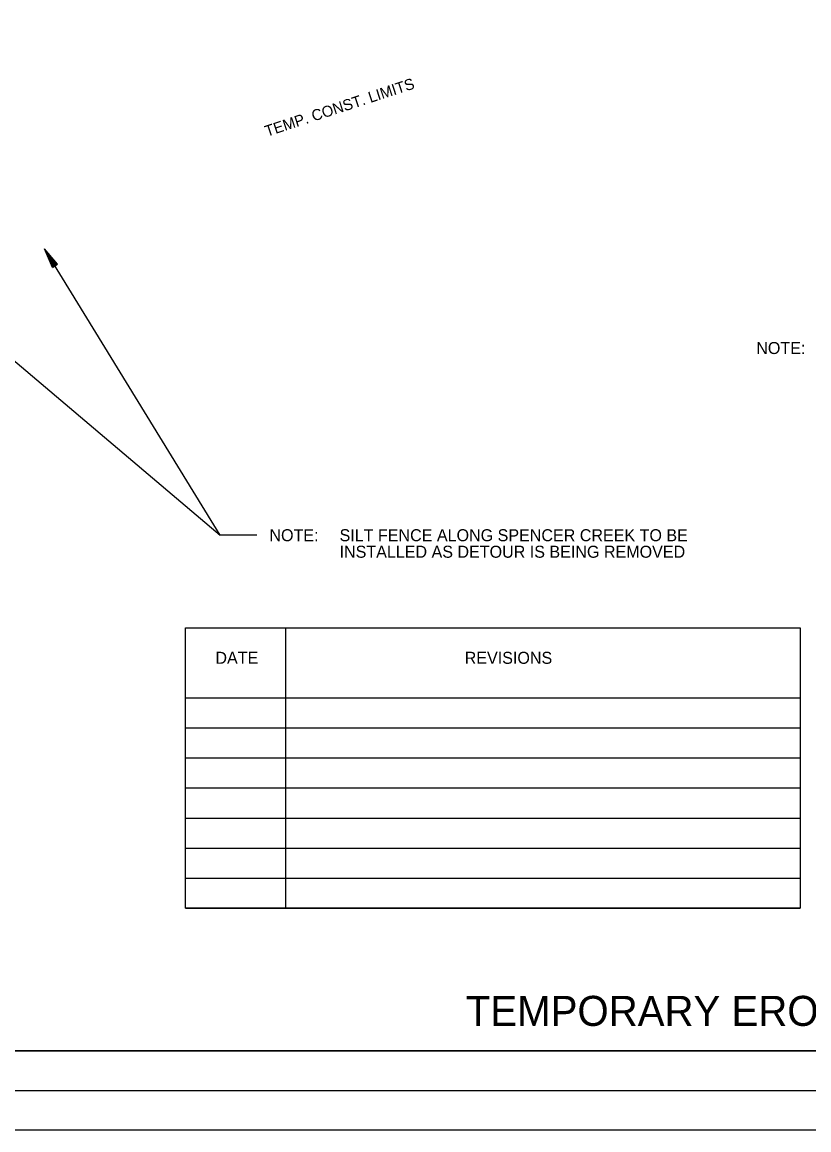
# Model space of a CAD drawing. Extents: x 9525 to 11605, y 9961 to 11067.
# Drawn here: x 10902 to 11295, y 9961 to 10514 of the extents above; entities that cross this region are included whole.
import ezdxf

# ---------------------------------------------------------------- set-up
doc = ezdxf.new("R2010")
doc.units = 0
for name, color, linetype in [('Clearing and Grubbing Temp Seeding', 7, 'Continuous'), ('GREEN_TXT', 7, 'Continuous'), ('SEAL-INFO', 7, 'Continuous'), ('Stage 1 Detour Temp Seeding', 7, 'Continuous'), ('Stage 1 Ditch Checks', 7, 'Continuous'), ('Stage 2 Main Temp Seeding', 7, 'Continuous'), ('Stage 3 Seeding MAIN', 7, 'Continuous')]:
    doc.layers.add(name, color=color, linetype=linetype)

msp = doc.modelspace()

# ---------------------------------------------------------------- linework, layer by layer
at = {"layer": 'GREEN_TXT'}
for p, q in [((11580.9, 10000), (10000, 10000)), ((9843.9, 9960.6), (11603.9, 9960.6))]:
    msp.add_line(p, q, dxfattribs=at)
at = {"layer": 'SEAL-INFO'}
msp.add_lwpolyline([(9937.96, 11046.77), (11604.66, 11046.77), (11604.66, 9980.09), (9937.96, 9980.09)], close=True, dxfattribs=at)
at = {"layer": 'Stage 1 Ditch Checks'}
msp.add_lwpolyline([(10000, 10000), (11580.9, 10000), (11580.3, 10963.3), (11365.4, 10963.3), (11357.31, 10959.87), (11348.49, 10961.4), (11348.26, 10977.9), (11169.6, 10977.9), (11169.6, 11027.3), (10000, 11027.3)], close=True, dxfattribs=at)
msp.add_lwpolyline([(10000, 10000), (11580.9, 10000), (11580.3, 10963.3), (11365.4, 10963.3), (11357.31, 10959.87), (11348.49, 10961.4), (11348.26, 10977.9), (11169.6, 10977.9), (11169.6, 11027.3), (10000, 11027.3)], close=True, dxfattribs=at)
at = {"layer": 'Stage 2 Main Temp Seeding'}
for p, q in [((11033.7, 10211.28), (11033.7, 10071.28)), ((11033.7, 10211.28), (11290.72, 10211.28)), ((10983.7, 10176.28), (11290.72, 10176.28)), ((10983.7, 10161.28), (11290.72, 10161.28)), ((10983.7, 10146.28), (11290.72, 10146.28)), ((10983.7, 10131.28), (11290.72, 10131.28)), ((10983.7, 10116.28), (11290.72, 10116.28)), ((10983.7, 10101.28), (11290.72, 10101.28)), ((10983.7, 10086.28), (11290.72, 10086.28)), ((10983.7, 10071.28), (11290.72, 10071.28))]:
    msp.add_line(p, q, dxfattribs=at)
msp.add_lwpolyline([(10983.7, 10211.28), (11290.72, 10211.28), (11290.72, 10071.28), (10983.7, 10071.28)], close=True, dxfattribs=at)
at = {"layer": 'Stage 3 Seeding MAIN'}
for p, q in [((10827.45, 10404.59), (11001.13, 10257.46)), ((10917.33, 10391.2), (10913.33, 10400.49)), ((10919.88, 10392.78), (10913.33, 10400.49)), ((10917.54, 10391.34), (10914.21, 10399.07)), ((10919.67, 10392.65), (10914.21, 10399.07)), ((10919.45, 10392.52), (10915.12, 10397.61)), ((10917.76, 10391.47), (10915.12, 10397.61)), ((10917.97, 10391.6), (10916, 10396.2)), ((10919.24, 10392.39), (10916, 10396.2)), ((10919.02, 10392.25), (10916.89, 10394.76)), ((10918.19, 10391.74), (10916.89, 10394.76)), ((10917.33, 10391.2), (10919.88, 10392.78)), ((10918.8, 10392.12), (10917.77, 10393.34)), ((10918.41, 10391.87), (10917.77, 10393.34))]:
    msp.add_line(p, q, dxfattribs=at)
msp.add_lwpolyline([(11019.43, 10257.46), (11001.13, 10257.46), (10913.33, 10400.49)], dxfattribs=at)

# ---------------------------------------------------------------- texts
at = {"layer": 'Clearing and Grubbing Temp Seeding'}
msp.add_text('TEMP. CONST. LIMITS', height=5.5, rotation=18.0985, dxfattribs=at).set_placement((11024.44, 10456.42))
at = {"layer": 'GREEN_TXT'}
msp.add_text('TEMPORARY EROSION CONTROL DETAILS', height=15, dxfattribs=at).set_placement((11123.73, 10012.5))
at = {"layer": 'Stage 1 Detour Temp Seeding'}
for s, p in [('DATE', (10998.7, 10193.28)), ('  REVISIONS', (11118.7, 10193.28))]:
    msp.add_text(s, height=6, dxfattribs=at).set_placement(p)
at = {"layer": 'Stage 3 Seeding MAIN'}
for s, p in [('NOTE:', (11268.73, 10347.95)), ('NOTE:', (11025.67, 10254.49)), ('SILT FENCE ALONG SPENCER CREEK TO BE ', (11060.69, 10254.49)), ('INSTALLED AS DETOUR IS BEING REMOVED', (11060.69, 10246.24))]:
    msp.add_text(s, height=6, dxfattribs=at).set_placement(p)

doc.saveas('drawing.dxf')
